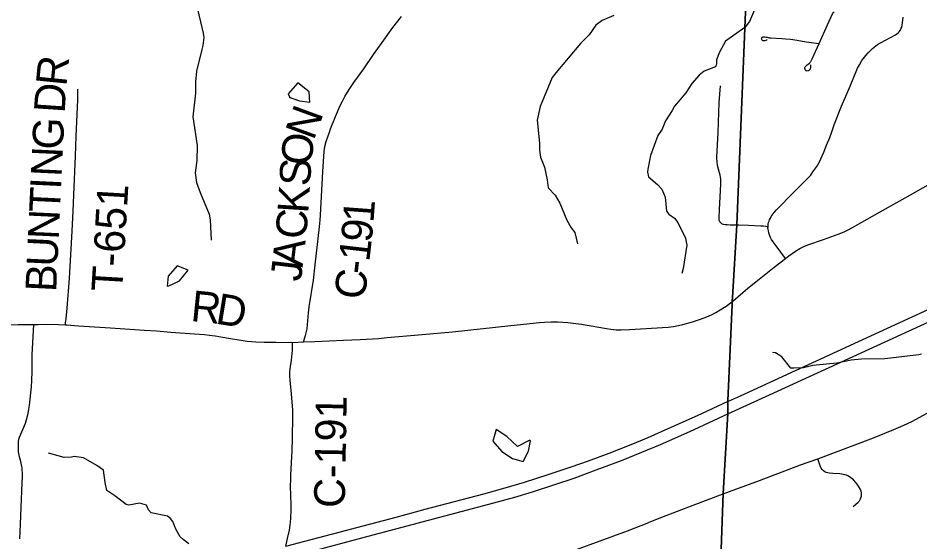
# Model space of a CAD drawing. Extents: x 0 to 34, y 0 to 22.
# Drawn here: x 4.217 to 5.879, y 16.675 to 17.641 of the extents above; entities that cross this region are included whole.
import ezdxf

# ---------------------------------------------------------------- set-up
doc = ezdxf.new("R2010")
doc.units = 0
for name, color, linetype in [('GM_X_County_Road', 7, 'Continuous'), ('GM_X_County_Road_Text', 7, 'Continuous'), ('GM_X_Interstate_Route', 7, 'Continuous'), ('GM_X_Minor_Lake', 7, 'Continuous'), ('GM_X_Minor_River', 7, 'Continuous'), ('GM_X_Rail_Line', 7, 'Continuous'), ('GM_X_Township_Road', 7, 'Continuous'), ('GM_X_Township_Road_Text', 7, 'Continuous'), ('GM_X_US_Route', 7, 'Continuous')]:
    doc.layers.add(name, color=color, linetype=linetype)

msp = doc.modelspace()

# ---------------------------------------------------------------- linework, layer by layer
at = {"layer": 'GM_X_County_Road'}
msp.add_line((4.7227, 17.043), (4.7429, 17.0438), dxfattribs=at)
for points in [[(4.7429, 17.0438), (4.7465, 17.0558), (4.7477, 17.0608), (4.7494, 17.0683), (4.7519, 17.0973), (4.7534, 17.1088), (4.7609, 17.1577), (4.7641, 17.1858), (4.7722, 17.256), (4.7734, 17.2683), (4.7741, 17.2776), (4.7784, 17.358), (4.7799, 17.3859), (4.7808, 17.3951), (4.7823, 17.4042), (4.7845, 17.4132), (4.7863, 17.4191), (4.7873, 17.422), (4.7905, 17.4307), (4.7927, 17.4365), (4.8019, 17.4594), (4.8103, 17.4795), (4.8143, 17.4879), (4.8188, 17.496), (4.8271, 17.5091), (4.8357, 17.522), (4.8537, 17.5472), (4.8717, 17.5735), (4.8878, 17.596), (4.9075, 17.6233), (4.9235, 17.6434)], [(5.6309, 17.1975), (5.6373, 17.2025), (5.6495, 17.2114), (5.6571, 17.2161), (5.6635, 17.2194), (5.6722, 17.2229), (5.7007, 17.2329), (5.7281, 17.2426), (5.7393, 17.247), (5.7476, 17.2511), (5.7585, 17.257), (5.7719, 17.2647), (5.8149, 17.2893), (5.8611, 17.3149), (5.9124, 17.3439), (5.9799, 17.3822), (6.0313, 17.4112), (6.0502, 17.4215), (6.0641, 17.4289), (6.0753, 17.4344), (6.0797, 17.4363), (6.0828, 17.4387), (6.0868, 17.4429)], [(5.5323, 17.1177), (5.5331, 17.1183), (5.5338, 17.1188), (5.5617, 17.1429), (5.5761, 17.1547), (5.6103, 17.1815), (5.6309, 17.1975)], [(4.7429, 17.0438), (4.7636, 17.0447), (4.8163, 17.0469), (4.8472, 17.0486), (4.8808, 17.0504), (4.8967, 17.0518), (4.9614, 17.0579), (5.017, 17.0628), (5.1249, 17.0743), (5.1774, 17.0795), (5.1867, 17.0803), (5.1991, 17.0808), (5.2115, 17.0809), (5.2208, 17.0805), (5.2301, 17.0797), (5.2394, 17.0786), (5.2548, 17.0764), (5.301, 17.0687), (5.3092, 17.0673), (5.3139, 17.0669), (5.3189, 17.0665), (5.3281, 17.0664), (5.3436, 17.0669), (5.4147, 17.0713), (5.4244, 17.0723), (5.4335, 17.0739), (5.442, 17.0759), (5.4598, 17.0811), (5.4745, 17.086), (5.486, 17.0904), (5.4945, 17.0941), (5.5028, 17.0981), (5.5107, 17.1028), (5.5215, 17.1099), (5.5323, 17.1177)], [(3.8202, 16.893), (3.8492, 16.9283), (3.8981, 16.9885), (3.9541, 17.0549), (3.9639, 17.0657), (3.9666, 17.0679), (3.9692, 17.0695), (3.9723, 17.0708), (3.9751, 17.0718), (3.978, 17.0726), (3.981, 17.0731), (3.9871, 17.0738), (3.9964, 17.0742), (4.0274, 17.0742), (4.1205, 17.0752), (4.167, 17.0757), (4.2167, 17.0758), (4.2456, 17.0761)], [(4.2456, 17.0761), (4.254, 17.0762), (4.2695, 17.0764), (4.2911, 17.076), (4.3039, 17.0754)], [(4.3039, 17.0754), (4.3066, 17.0753), (4.3283, 17.0738), (4.3871, 17.0698), (4.449, 17.0657), (4.4717, 17.0643), (4.4984, 17.062), (4.5417, 17.0586), (4.5602, 17.0575), (4.5697, 17.0566), (4.5799, 17.0553), (4.5902, 17.0535), (4.6085, 17.0501), (4.6238, 17.0475), (4.6392, 17.0455), (4.6547, 17.0442), (4.6702, 17.0435), (4.692, 17.0433), (4.7227, 17.043)], [(4.7103, 16.6674), (4.7135, 16.6819), (4.7167, 16.6972), (4.7181, 16.7064), (4.7196, 16.7188), (4.7202, 16.7344), (4.7202, 16.7438), (4.719, 16.778), (4.7191, 16.7904), (4.7194, 16.7996), (4.72, 16.809), (4.7204, 16.8216), (4.7218, 16.8433), (4.7222, 16.8657), (4.7232, 16.907), (4.7231, 16.9181), (4.7219, 16.9336), (4.72, 16.9551), (4.7179, 16.9729), (4.7173, 16.9813), (4.7178, 16.9889), (4.719, 16.9986), (4.7207, 17.0104), (4.7223, 17.0286), (4.7225, 17.0362), (4.7227, 17.043)]]:
    msp.add_lwpolyline(points, dxfattribs=at)
at = {"layer": 'GM_X_Interstate_Route'}
for points in [[(4.7609, 16.6592), (4.7838, 16.6653), (4.8529, 16.6836), (5.0932, 16.7471), (5.132, 16.758), (5.1647, 16.7679), (5.2061, 16.7812), (5.2414, 16.7931), (5.2823, 16.8079), (5.3288, 16.8255), (5.3663, 16.8405), (5.4006, 16.855), (5.4545, 16.879), (5.5249, 16.9113), (5.6013, 16.9464), (5.9542, 17.1082), (6.0643, 17.1589), (6.1173, 17.1828)], [(4.7103, 16.6674), (4.9132, 16.7211), (4.9672, 16.7356), (5.0753, 16.7641), (5.1143, 16.7749), (5.1501, 16.7855), (5.1915, 16.7987), (5.2357, 16.8135), (5.268, 16.8248), (5.3059, 16.839), (5.3464, 16.8549), (5.378, 16.868), (5.415, 16.8842), (5.4688, 16.9086), (5.5251, 16.9345), (5.5258, 16.9348), (5.5479, 16.9448), (5.6495, 16.9915), (5.7653, 17.0446), (5.9177, 17.1148)]]:
    msp.add_lwpolyline(points, dxfattribs=at)
at = {"layer": 'GM_X_Minor_Lake'}
for points in [[(4.7354, 17.4883), (4.7547, 17.4856), (4.7532, 17.5049), (4.732, 17.5213), (4.7146, 17.5011), (4.7177, 17.4942)], [(4.7161, 17.4947), (4.7354, 17.4883), (4.7547, 17.4856), (4.7532, 17.5049), (4.732, 17.5213), (4.7146, 17.5011), (4.7161, 17.4977)], [(4.7177, 17.4942), (4.7354, 17.4883)], [(4.5303, 17.176), (4.5102, 17.1843), (4.4936, 17.1653), (4.4917, 17.1464), (4.4943, 17.1471)], [(4.4943, 17.1471), (4.514, 17.1566), (4.5303, 17.176), (4.5102, 17.1843), (4.4936, 17.1653), (4.4917, 17.1464), (4.4917, 17.1467)], [(4.4943, 17.1471), (4.514, 17.1566), (4.5303, 17.176)], [(5.1599, 16.863), (5.1368, 16.8509), (5.1175, 16.8698), (5.0978, 16.8827), (5.0918, 16.8611), (5.108, 16.8418)], [(5.1599, 16.863), (5.1368, 16.8509), (5.1175, 16.8698), (5.0978, 16.8827), (5.0918, 16.8611), (5.108, 16.8418), (5.1277, 16.8289), (5.1478, 16.8235), (5.1576, 16.8425), (5.161, 16.8619), (5.1599, 16.863)], [(5.108, 16.8418), (5.1277, 16.8289), (5.1478, 16.8235), (5.1576, 16.8425), (5.161, 16.8619), (5.1599, 16.863)]]:
    msp.add_lwpolyline(points, dxfattribs=at)
at = {"layer": 'GM_X_Minor_River'}
for points in [[(4.5448, 17.6677), (4.558, 17.6131), (4.5588, 17.6052), (4.557, 17.5904), (4.5551, 17.5831), (4.5455, 17.5432), (4.5437, 17.5235), (4.5438, 17.5026), (4.5387, 17.4589), (4.5465, 17.4058), (4.5459, 17.3781), (4.543, 17.3557), (4.5457, 17.3375), (4.5523, 17.3193), (4.5691, 17.2795), (4.571, 17.2689), (4.5727, 17.2313)], [(5.5757, 17.6605), (5.5649, 17.6346), (5.5559, 17.6232), (5.5204, 17.5983), (5.5092, 17.5782), (5.5039, 17.5637), (5.504, 17.5557), (5.5017, 17.5508), (5.481, 17.5431), (5.4719, 17.5354), (5.4584, 17.5202), (5.4471, 17.5027), (5.4264, 17.4786), (5.4223, 17.4706), (5.4099, 17.4516), (5.4036, 17.436), (5.3957, 17.4246), (5.3819, 17.3877), (5.3771, 17.3622), (5.3767, 17.3565), (5.3787, 17.3482), (5.395, 17.3338), (5.403, 17.3255), (5.4091, 17.3107), (5.4119, 17.2849), (5.4157, 17.2793), (5.4263, 17.2721), (5.4328, 17.2638), (5.4466, 17.2354), (5.4489, 17.2225), (5.4423, 17.1792), (5.4397, 17.1701)], [(5.3144, 17.6458), (5.2933, 17.6366), (5.2816, 17.6278), (5.2692, 17.6099), (5.253, 17.5942), (5.2075, 17.5397), (5.2011, 17.5313), (5.179, 17.4777), (5.1731, 17.4526), (5.1775, 17.4105), (5.1776, 17.3972), (5.1795, 17.3847), (5.1868, 17.3657), (5.1918, 17.3426), (5.1934, 17.3278), (5.2063, 17.3146), (5.2151, 17.2994), (5.2278, 17.2684), (5.2358, 17.2544), (5.243, 17.2457), (5.2476, 17.2244)], [(5.8815, 17.0214), (5.8766, 17.0202), (5.8709, 17.0194), (5.8142, 17.0127), (5.7707, 17.0124), (5.7522, 17.0101), (5.7254, 17.0046), (5.6811, 17.0002), (5.6638, 16.9963), (5.646, 16.9954), (5.6407, 16.9958), (5.6243, 17.0166), (5.6122, 17.0241), (5.6069, 17.0245)], [(4.5317, 16.6719), (4.5207, 16.6795), (4.5157, 16.6848), (4.5073, 16.6991), (4.5019, 16.7128), (4.4978, 16.7184), (4.4921, 16.723), (4.4621, 16.7289), (4.4572, 16.7345), (4.4534, 16.7429), (4.4405, 16.7466), (4.4208, 16.7431), (4.4159, 16.7446), (4.395, 16.7604), (4.3806, 16.7702), (4.3771, 16.7846), (4.3744, 16.8077), (4.3622, 16.8164), (4.3372, 16.8303), (4.3201, 16.8325), (4.3152, 16.8313), (4.3016, 16.8309), (4.2728, 16.8387)]]:
    msp.add_lwpolyline(points, dxfattribs=at)
at = {"layer": 'GM_X_Rail_Line'}
for points in [[(5.6047, 18.8149), (5.5414, 17.2599), (5.5331, 17.1257), (5.5329, 17.1188), (5.5325, 17.1129), (5.5249, 16.9351), (5.5246, 16.9118), (5.5158, 16.7643), (5.4957, 16.1987)], [(5.4957, 16.1987), (5.5158, 16.7643), (5.5246, 16.9118), (5.5249, 16.9351), (5.5325, 17.1129), (5.5329, 17.1188), (5.5331, 17.1257), (5.5414, 17.2599), (5.6047, 18.8149)]]:
    msp.add_lwpolyline(points, dxfattribs=at)
at = {"layer": 'GM_X_Township_Road'}
for points in [[(5.6928, 17.5941), (5.7084, 17.6281), (5.7173, 17.6486), (5.7189, 17.6507), (5.7204, 17.652)], [(5.5987, 17.2561), (5.5987, 17.2579), (5.5992, 17.261), (5.5998, 17.2643), (5.6007, 17.2667), (5.6016, 17.2692), (5.603, 17.2722), (5.6046, 17.2749), (5.6064, 17.2776), (5.61, 17.2826), (5.6141, 17.2873), (5.6462, 17.32), (5.6774, 17.3515), (5.6816, 17.3571), (5.6852, 17.3621), (5.6887, 17.3674), (5.6934, 17.3757), (5.7016, 17.3936), (5.7067, 17.4063), (5.7124, 17.4207), (5.7162, 17.4311), (5.7213, 17.4458), (5.7341, 17.4787), (5.7498, 17.5152), (5.7639, 17.5482), (5.7671, 17.5544), (5.7717, 17.5623), (5.7789, 17.5716), (5.783, 17.5766), (5.7913, 17.5844), (5.8007, 17.5918), (5.806, 17.5954), (5.8334, 17.6098), (5.8362, 17.6116), (5.8386, 17.6135), (5.8406, 17.6155), (5.8425, 17.6181), (5.8437, 17.6207), (5.845, 17.6241), (5.8457, 17.6273), (5.8478, 17.6423)], [(5.5971, 17.6011), (5.5957, 17.6001), (5.5944, 17.5994), (5.5928, 17.599), (5.5913, 17.5989), (5.5896, 17.5991), (5.5885, 17.5997), (5.5878, 17.6003), (5.5874, 17.601), (5.5871, 17.6024), (5.587, 17.6037), (5.5873, 17.6047), (5.588, 17.6054), (5.5888, 17.6058), (5.5895, 17.606), (5.5903, 17.6062), (5.5914, 17.6063), (5.5926, 17.6062), (5.5952, 17.6057), (5.597, 17.6053), (5.5989, 17.6049), (5.601, 17.6046), (5.6042, 17.6046), (5.624, 17.6033), (5.6311, 17.6027), (5.6399, 17.6017), (5.6522, 17.5998), (5.669, 17.597), (5.6928, 17.5941)], [(5.677, 17.5543), (5.677, 17.5512), (5.6768, 17.5491), (5.6766, 17.5478), (5.6763, 17.5469), (5.6756, 17.5458), (5.6748, 17.545), (5.6738, 17.5442), (5.6724, 17.5435), (5.6711, 17.5432), (5.6697, 17.5433), (5.6685, 17.5437), (5.6675, 17.5446), (5.6669, 17.5459), (5.6666, 17.5479), (5.6668, 17.5494), (5.6674, 17.5507), (5.6682, 17.552), (5.6694, 17.5533), (5.6708, 17.5545), (5.6726, 17.5561), (5.675, 17.5578), (5.6764, 17.559), (5.6773, 17.5599), (5.6778, 17.5608), (5.68, 17.5657), (5.6928, 17.5941)], [(4.3039, 17.0754), (4.3044, 17.0793), (4.3054, 17.087), (4.3075, 17.1059), (4.3113, 17.1612), (4.3158, 17.2368), (4.3184, 17.2844), (4.3198, 17.315), (4.3226, 17.3864), (4.324, 17.4232), (4.3263, 17.4763), (4.3268, 17.49), (4.327, 17.5022), (4.3272, 17.5098)], [(5.5395, 17.2594), (5.5373, 17.2594), (5.5289, 17.2594), (5.5236, 17.2595), (5.5215, 17.2596), (5.5197, 17.2598), (5.5166, 17.2603), (5.5149, 17.2609), (5.5135, 17.2617), (5.5121, 17.2627), (5.511, 17.2639), (5.5101, 17.2655), (5.5094, 17.2672), (5.509, 17.2686), (5.5089, 17.2702), (5.5089, 17.2734), (5.5095, 17.2882), (5.5116, 17.3349), (5.5115, 17.3445), (5.511, 17.3478), (5.5105, 17.351), (5.5061, 17.3664), (5.5054, 17.3708), (5.5049, 17.3744), (5.5044, 17.3843), (5.5068, 17.4299), (5.5089, 17.4852), (5.5099, 17.5006), (5.5111, 17.5161)], [(5.5987, 17.2561), (5.5906, 17.2571), (5.5853, 17.2575), (5.5627, 17.2587), (5.5449, 17.2594), (5.5417, 17.2594), (5.5395, 17.2594)], [(5.6309, 17.1975), (5.6135, 17.2211), (5.608, 17.2284), (5.605, 17.2326), (5.6032, 17.2362), (5.6021, 17.2393), (5.6004, 17.2451), (5.5995, 17.2484), (5.5991, 17.2509), (5.5986, 17.2543), (5.5987, 17.2561)], [(4.2202, 16.681), (4.221, 16.7083), (4.2219, 16.7237), (4.2227, 16.739), (4.2242, 16.784), (4.2247, 16.7961), (4.2247, 16.8022), (4.2244, 16.8084), (4.2242, 16.8119), (4.2238, 16.8145), (4.2227, 16.8206), (4.2219, 16.8236), (4.2194, 16.8323), (4.2181, 16.8382), (4.2176, 16.8412), (4.2174, 16.8442), (4.2173, 16.8473), (4.2174, 16.8535), (4.2178, 16.8606), (4.2184, 16.8644), (4.2197, 16.8684), (4.2219, 16.8742), (4.2255, 16.8828), (4.2303, 16.8942), (4.233, 16.9031), (4.2354, 16.912), (4.2369, 16.9199), (4.2381, 16.9276), (4.2414, 16.9612), (4.2423, 16.9736), (4.2429, 16.9891), (4.2426, 17.0015), (4.2429, 17.0201), (4.2456, 17.0761)], [(5.7555, 16.7406), (5.7649, 16.7489), (5.767, 16.7512), (5.7687, 16.7538), (5.7699, 16.7567), (5.7707, 16.7597), (5.7709, 16.7628), (5.7707, 16.766), (5.7701, 16.769), (5.769, 16.772), (5.7676, 16.7748), (5.7643, 16.7801), (5.7605, 16.7851), (5.7562, 16.7896), (5.7513, 16.7937), (5.7488, 16.7955), (5.746, 16.797), (5.7432, 16.7983), (5.7402, 16.7992), (5.7371, 16.7998), (5.7309, 16.8006), (5.7184, 16.8014), (5.7121, 16.802), (5.709, 16.8026), (5.706, 16.8035), (5.7032, 16.8048), (5.7007, 16.8066), (5.6985, 16.8088), (5.6966, 16.8114), (5.6948, 16.8156), (5.6904, 16.8287)]]:
    msp.add_lwpolyline(points, dxfattribs=at)
at = {"layer": 'GM_X_US_Route'}
for points in [[(5.6904, 16.8287), (5.7932, 16.8674), (5.814, 16.8757), (5.8308, 16.8826), (5.8479, 16.8899), (5.8647, 16.898), (5.8839, 16.9083), (5.9388, 16.9379), (5.9639, 16.9522), (5.9866, 16.9648), (6.0056, 16.9748), (6.0254, 16.9856), (6.0317, 16.9888)], [(5.3798, 16.7117), (5.4028, 16.7208), (5.461, 16.7428), (5.5161, 16.7638), (5.5393, 16.7724), (5.583, 16.7887), (5.6586, 16.8173), (5.6904, 16.8287)], [(4.6164, 16.4265), (4.6348, 16.4333), (4.6639, 16.4441), (4.6989, 16.4572), (4.728, 16.4679), (4.7543, 16.4776), (4.798, 16.4938), (4.8241, 16.5037), (4.8503, 16.5136), (4.9376, 16.5462), (4.9696, 16.5582), (5.0133, 16.5741), (5.0424, 16.5852), (5.0686, 16.5949), (5.0947, 16.6048), (5.118, 16.6135), (5.1616, 16.6298), (5.1907, 16.6407), (5.2169, 16.6504), (5.246, 16.6614), (5.2893, 16.6772), (5.3397, 16.696), (5.3789, 16.7113), (5.3798, 16.7117)]]:
    msp.add_lwpolyline(points, dxfattribs=at)

# ---------------------------------------------------------------- texts
at = {"layer": 'GM_X_County_Road_Text'}
for s, height, rotation, p in [('N', 0.0568, 69.936, (4.7615, 17.4138)), ('O', 0.0568, 83.7109, (4.7569, 17.3676)), ('S', 0.0568, 86.5004, (4.7546, 17.3301)), ('K', 0.0568, 86.3406, (4.7514, 17.28)), ('C', 0.0568, 84.7111, (4.747, 17.2318)), ('1', 0.0568, 85.7936, (4.8716, 17.2625)), ('9', 0.0568, 84.2157, (4.8679, 17.2259)), ('A', 0.0568, 83.3593, (4.741, 17.1807)), ('1', 0.0568, 83.4873, (4.8639, 17.1904)), ('J', 0.0568, 83.2088, (4.7379, 17.154)), ('-', 0.0568, 83.1458, (4.861, 17.1669)), ('C', 0.0568, 83.0279, (4.8554, 17.1204)), ('R', 0.0568, 354.143, (4.5335, 17.0826)), ('D', 0.0568, 350.6736, (4.579, 17.078)), ('C-191', 0.05682, 88.9298, (4.8187, 16.7376))]:
    msp.add_text(s, height=height, rotation=rotation, dxfattribs=at).set_placement(p)
at = {"layer": 'GM_X_Township_Road_Text'}
for s, height, rotation, p in [('R', 0.0568, 84.2688, (4.3058, 17.514)), ('D', 0.0568, 86.1612, (4.3025, 17.4646)), ('G', 0.0568, 87.2778, (4.2993, 17.3974)), ('N', 0.0568, 87.2815, (4.2969, 17.3475)), ('I', 0.0568, 87.2826, (4.2958, 17.3242)), ('T', 0.0568, 87.2843, (4.2938, 17.2817)), ('T-651', 0.05682, 86.6333, (4.4085, 17.1354)), ('N', 0.0568, 87.2828, (4.2915, 17.2318)), ('U', 0.0568, 87.2815, (4.2891, 17.1818)), ('B', 0.0568, 87.2826, (4.2869, 17.1352))]:
    msp.add_text(s, height=height, rotation=rotation, dxfattribs=at).set_placement(p)

doc.saveas('drawing.dxf')
